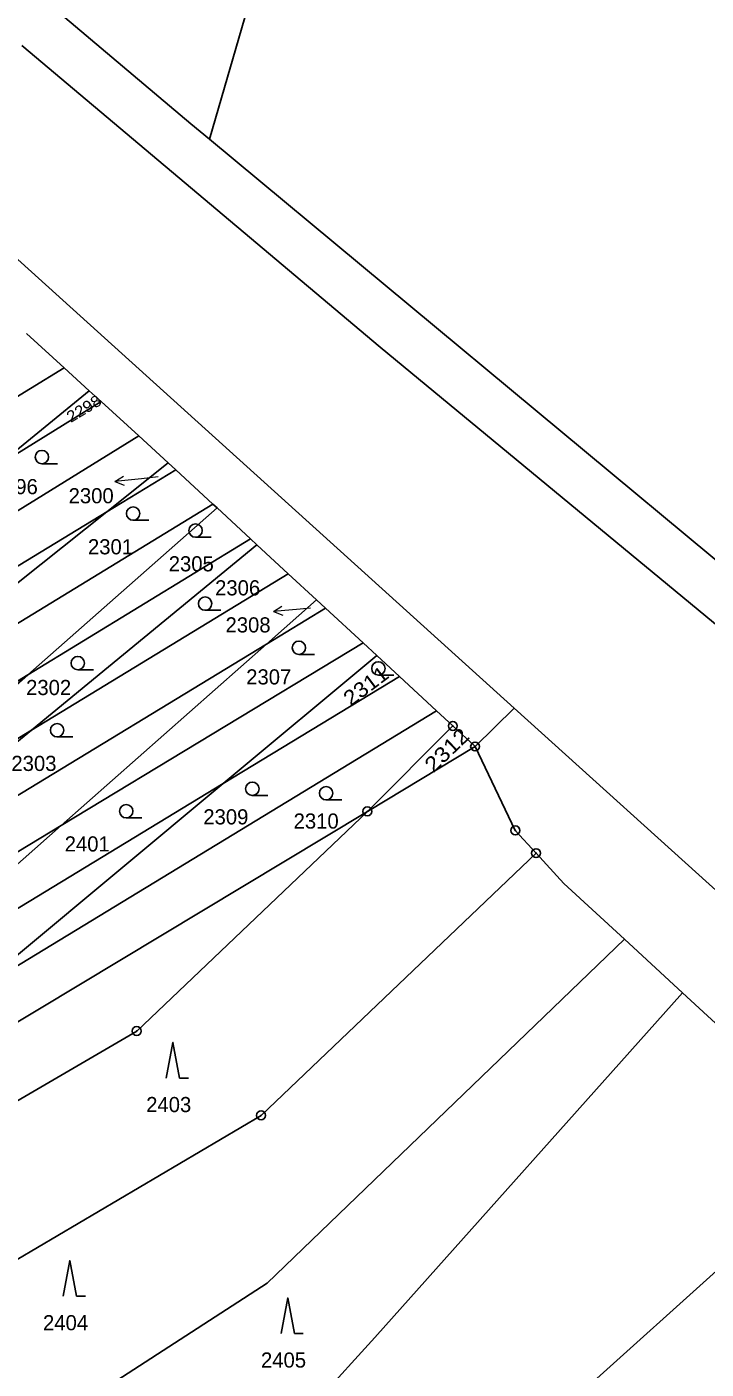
# Model space of a CAD drawing. Extents: x -606517 to -602431, y -1183120 to -1179397.
# Drawn here: x -604891 to -604814.8, y -1180857.3 to -1180706.6 of the extents above; entities that cross this region are included whole.
import ezdxf

# ---------------------------------------------------------------- set-up
doc = ezdxf.new("R2010")
doc.units = 0
doc.header["$LTSCALE"] = 0.68
for name, color, linetype, lineweight in [('1', 7, 'Continuous', 25), ('3', 7, 'Continuous', 25), ('7', 7, 'Continuous', 13), ('8', 7, 'Continuous', 25)]:
    doc.layers.add(name, color=color, linetype=linetype, lineweight=lineweight)
doc.layers.add('2', color=7, linetype='Continuous')

msp = doc.modelspace()

# ---------------------------------------------------------------- linework, layer by layer
at = {"layer": '1'}
for p, q in [((-604870.51, -1180719.22), (-604831.4, -1180584.66)), ((-604956.42, -1180674.5), (-604836.32, -1180783.1)), ((-604887.93, -1180704.55), (-604872.6, -1180717.48)), ((-604851.37, -1180742.57), (-604891.57, -1180708.68)), ((-604872.6, -1180717.48), (-604870.51, -1180719.22)), ((-604870.51, -1180719.22), (-604799.44, -1180778.35)), ((-604891.02, -1180741.04), (-604886.8, -1180744.87)), ((-604803.76, -1180781.91), (-604851.37, -1180742.57)), ((-604886.8, -1180744.87), (-604944.67, -1180780.46)), ((-604886.8, -1180744.87), (-604884, -1180747.45)), ((-604884, -1180747.45), (-604894.34, -1180755.88)), ((-604894.34, -1180755.88), (-604882.66, -1180748.67)), ((-604882.66, -1180748.67), (-604884, -1180747.45)), ((-604882.66, -1180748.67), (-604878.42, -1180752.5)), ((-604878.42, -1180752.5), (-604936.12, -1180788.17)), ((-604878.42, -1180752.5), (-604875.14, -1180755.54)), ((-604882.04, -1180761.04), (-604875.14, -1180755.54)), ((-604875.14, -1180755.54), (-604874.29, -1180756.32)), ((-604882.04, -1180761.04), (-604874.29, -1180756.32)), ((-604874.29, -1180756.32), (-604870.12, -1180760.18)), ((-604927.91, -1180795.45), (-604870.12, -1180760.18)), ((-604890.89, -1180779.33), (-604869.66, -1180760.61)), ((-604870.12, -1180760.18), (-604869.66, -1180760.61)), ((-604869.66, -1180760.61), (-604865.9, -1180764.09)), ((-604882.04, -1180761.04), (-604932.19, -1180791.66)), ((-604915.74, -1180787.95), (-604882.04, -1180761.04)), ((-604865.9, -1180764.09), (-604890.89, -1180779.33)), ((-604890.49, -1180785.54), (-604865.2, -1180764.73)), ((-604865.9, -1180764.09), (-604865.2, -1180764.73)), ((-604865.2, -1180764.73), (-604861.68, -1180767.99)), ((-604890.49, -1180785.54), (-604861.68, -1180767.99)), ((-604861.68, -1180767.99), (-604858.51, -1180770.92)), ((-604864.13, -1180775.9), (-604858.51, -1180770.92)), ((-604858.51, -1180770.92), (-604857.5, -1180771.86)), ((-604857.5, -1180771.86), (-604864.13, -1180775.9)), ((-604857.5, -1180771.86), (-604853.28, -1180775.75)), ((-604853.28, -1180775.75), (-604887.16, -1180796.25)), ((-604853.28, -1180775.75), (-604851.74, -1180777.18)), ((-604915.04, -1180806.88), (-604864.13, -1180775.9)), ((-604887.16, -1180796.25), (-604864.13, -1180775.9)), ((-604868.99, -1180791.56), (-604851.74, -1180777.18)), ((-604851.74, -1180777.18), (-604849.2, -1180779.54)), ((-604923.61, -1180799.27), (-604890.89, -1180779.33)), ((-604905.86, -1180792.52), (-604890.89, -1180779.33)), ((-604868.99, -1180791.56), (-604849.2, -1180779.54)), ((-604849.2, -1180779.54), (-604845.03, -1180783.39)), ((-604836.32, -1180783.1), (-604840.71, -1180787.39)), ((-604836.32, -1180783.1), (-604766.15, -1180846.54)), ((-604902.27, -1180818.21), (-604845.03, -1180783.39)), ((-604845.03, -1180783.39), (-604843.21, -1180785.08)), ((-604890.49, -1180785.54), (-604919.31, -1180803.09)), ((-604915.71, -1180806.28), (-604890.49, -1180785.54)), ((-604852.8, -1180794.67), (-604843.21, -1180785.08)), ((-604843.21, -1180785.08), (-604840.71, -1180787.39)), ((-604840.71, -1180787.39), (-604852.8, -1180794.67)), ((-604836.2, -1180796.81), (-604840.71, -1180787.39)), ((-604868.99, -1180791.56), (-604906.57, -1180814.4)), ((-604892.16, -1180810.88), (-604868.99, -1180791.56)), ((-604852.8, -1180794.67), (-604898.08, -1180821.93)), ((-604878.67, -1180819.33), (-604852.8, -1180794.67)), ((-604910.85, -1180810.59), (-604887.16, -1180796.25)), ((-604897.57, -1180805.46), (-604887.16, -1180796.25)), ((-604833.87, -1180799.36), (-604836.2, -1180796.81)), ((-604833.87, -1180799.36), (-604864.72, -1180828.8)), ((-604830.76, -1180802.76), (-604833.87, -1180799.36)), ((-604823.97, -1180809.02), (-604830.76, -1180802.76)), ((-604864.02, -1180847.64), (-604823.97, -1180809.02)), ((-604817.43, -1180815.05), (-604823.97, -1180809.02)), ((-604851.96, -1180853.72), (-604817.43, -1180815.05)), ((-604817.43, -1180815.05), (-604798.46, -1180832.55)), ((-604939.48, -1180854.86), (-604878.67, -1180819.33)), ((-604864.72, -1180828.8), (-604935.53, -1180870.63)), ((-604883.82, -1180909.45), (-604798.46, -1180832.55)), ((-604898.22, -1180869.74), (-604864.02, -1180847.64)), ((-604884.17, -1180889.23), (-604851.96, -1180853.72))]:
    msp.add_line(p, q, dxfattribs=at)
at = {"layer": '3'}
for p, q in [((-604889.313, -1180755.64), (-604887.563, -1180755.64)), ((-604879.073, -1180761.99), (-604877.323, -1180761.99)), ((-604872.073, -1180763.9), (-604870.323, -1180763.9)), ((-604870.993, -1180772.1), (-604869.243, -1180772.1)), ((-604860.483, -1180777.05), (-604858.733, -1180777.05)), ((-604885.283, -1180778.78), (-604883.533, -1180778.78)), ((-604851.563, -1180779.38), (-604849.813, -1180779.38)), ((-604887.603, -1180786.31), (-604885.853, -1180786.31)), ((-604865.703, -1180792.88), (-604863.953, -1180792.88)), ((-604857.423, -1180793.38), (-604855.673, -1180793.38)), ((-604879.853, -1180795.4), (-604878.103, -1180795.4)), ((-604873.86, -1180824.61), (-604872.864, -1180824.61)), ((-604885.43, -1180849.1), (-604884.434, -1180849.1)), ((-604860.98, -1180853.29), (-604859.984, -1180853.29))]:
    msp.add_line(p, q, dxfattribs=at)
for points in [[(-604873.86, -1180824.61), (-604874.61, -1180820.61), (-604875.36, -1180824.61)], [(-604885.43, -1180849.1), (-604886.18, -1180845.1), (-604886.93, -1180849.1)], [(-604860.98, -1180853.29), (-604861.73, -1180849.29), (-604862.48, -1180853.29)]]:
    msp.add_lwpolyline(points, dxfattribs=at)
for centre in [(-604889.3129, -1180754.8898), (-604879.0729, -1180761.2398), (-604872.0729, -1180763.1498), (-604870.9929, -1180771.3498), (-604860.4829, -1180776.2998), (-604885.2829, -1180778.0298), (-604851.5629, -1180778.6298), (-604887.6029, -1180785.5598), (-604865.7029, -1180792.1298), (-604857.4229, -1180792.6298), (-604879.8529, -1180794.6498)]:
    msp.add_circle(centre, 0.75, dxfattribs=at)
at = {"layer": '7'}
for p, q in [((-604881.115, -1180757.654), (-604880.066, -1180758.047)), ((-604863.33, -1180772.222), (-604862.288, -1180772.633))]:
    msp.add_line(p, q, dxfattribs=at)
for points in [[(-604876.28, -1180757.13), (-604878.13, -1180757.34), (-604881.115, -1180757.654), (-604880.171, -1180757.051)], [(-604859.17, -1180771.86), (-604860.34, -1180771.96), (-604863.33, -1180772.222), (-604862.376, -1180771.635)]]:
    msp.add_lwpolyline(points, dxfattribs=at)
at = {"layer": '8'}
for centre, radius in [((-604843.21, -1180785.0799), 0.5), ((-604843.21, -1180785.0799), 0.0303), ((-604840.71, -1180787.3899), 0.5), ((-604840.71, -1180787.3899), 0.0303), ((-604852.8, -1180794.6699), 0.5), ((-604852.8, -1180794.6699), 0.0303), ((-604836.2, -1180796.8099), 0.5), ((-604836.2, -1180796.8099), 0.0303), ((-604833.87, -1180799.3599), 0.5), ((-604833.87, -1180799.3599), 0.0303), ((-604878.67, -1180819.3299), 0.5), ((-604878.67, -1180819.3299), 0.0303), ((-604864.72, -1180828.7999), 0.5), ((-604864.72, -1180828.7999), 0.0303)]:
    msp.add_circle(centre, radius, dxfattribs=at)

# ---------------------------------------------------------------- texts
at = {"layer": '2'}
for s, height, rotation, width, p in [('2298', 1.27, 31, 1.1, (-604886.056, -1180751.072)), ('2311', 1.7, 37, 1.1, (-604854.674, -1180782.929)), ('2312', 1.7, 44, 1.15, (-604845.384, -1180790.415))]:
    msp.add_text(s, height=height, rotation=rotation, dxfattribs=dict(at, width=width)).set_placement(p)
for s, p in [('2296', (-604894.82, -1180759.065)), ('2300', (-604886.31, -1180760.085)), ('2301', (-604884.14, -1180765.815)), ('2305', (-604875.08, -1180767.725)), ('2306', (-604869.88, -1180770.425)), ('2308', (-604868.71, -1180774.585)), ('2307', (-604866.39, -1180780.425)), ('2302', (-604891.08, -1180781.615)), ('2303', (-604892.73, -1180790.135)), ('2309', (-604871.2, -1180796.135)), ('2310', (-604861.07, -1180796.605)), ('2401', (-604886.75, -1180799.175)), ('2403', (-604877.61, -1180828.435)), ('2404', (-604889.18, -1180852.925)), ('2405', (-604864.73, -1180857.115))]:
    msp.add_text(s, height=1.7, dxfattribs=at).set_placement(p)

doc.saveas('drawing.dxf')
